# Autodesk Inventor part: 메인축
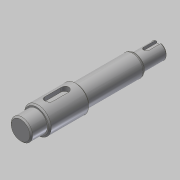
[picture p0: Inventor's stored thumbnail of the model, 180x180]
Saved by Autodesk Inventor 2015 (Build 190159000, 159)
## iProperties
Created: 2019-03
Part Number: 메인축
Material: 강철, 연강
Document SubType Name: Modeling
Designer: mduedu
Density: 1 g/cm^3
Appearance: 강철
Author: mduedu
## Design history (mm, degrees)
sketch "스케치1"
  geometry: L1 (0, 0)-(12, 0); L2 (12, 0)-(12, 8); L3 (12, 8)-(0, 8); L4 (0, 8)-(0, 0); L5 (12, 0)-(42, 0); L6 (42, 0)-(42, 10); L7 (42, 10)-(12, 10); L8 (12, 10)-(12, 0); L9 (42, 0)-(86, 0); L10 (86, 0)-(86, 8); L11 (86, 8)-(42, 8); L12 (42, 8)-(42, 0); L13 (86, 0)-(104, 0); L14 (104, 0)-(104, 6); L15 (104, 6)-(86, 6); L16 (86, 6)-(86, 0)
  constraints: 32 end point, 8 parallel, 4 horizontal, 4 perpendicular
  dimensions: "d0" = 16 diameter of L3 L1; "d2" = 20 diameter of L7 L5; "d3" = 16 diameter of L11 L9; "d4" = 12 diameter of L15 L13; "d5" = 12 distance of L2.end L3.end; "d6" = 30 distance of L6.end L7.end; "d7" = 86 distance between parallel lines of L10 L4; "d8" = 104 distance between parallel lines of L14 L4
revolve "회전1" sketch "스케치1" stored, may be unused: angle "d9" = 90 deg
node "작업 평면1"
sketch "스케치2" dims "d10" = 18
  geometry: L1 (6, -3)-(-6, -3); L2 (-6, -3)-(-6, 3); L3 (-6, 3)-(6, 3); L4 (6, 3)-(6, -3); L5 (15, 10)-(15, -10) reference; 3 further points
  constraints: 8 end point, 2 midpoint, 2 parallel, 2 vertical alignment, 1 horizontal, 1 horizontal alignment, 1 perpendicular, 4 other
  dimensions: "d12" = 6 distance between parallel lines of L3 L1; "d13" = 6 dimension on L5
extrude "돌출1" cut sketch "스케치2" distance "d14" = 3.5; taper "d15" = 0 deg
node "작업 평면2"
sketch "스케치3"
  geometry: L1 (-9, 6)-(-9, -6) reference; L2 (1, -2)-(-9, -2); L3 (1, 2)-(-9, 2); A1 r 2 centre (1, 0) between (1, -2) and (1, 2); 2 further points
  constraints: 4 end point, 2 point on circle, 2 point on line, 2 tangent, 1 centre point, 1 horizontal alignment, 1 midpoint, 1 parallel, 1 perpendicular
  dimensions: "d16" = 12 dimension on A1 L1; "d17" = 4 distance between parallel lines of L3 L2
extrude "돌출2" cut sketch "스케치3" distance "d18" = 2.5; taper "d19" = 0 deg
chamfer "모따기1" distance "d20" = 1; stored, may be unused: second distance "d21" = 2, angle "d22" = 45 deg
chamfer "모따기2" distance "d23" = 1; stored, may be unused: second distance "d24" = 2, angle "d25" = 45 deg
chamfer "모따기3" distance "d26" = 1.73; stored, may be unused: second distance "d27" = 2, angle "d28" = 30 deg
fillet "모깎기2" dims "d31" = 1, "d32" = 2
node "솔리드1"
